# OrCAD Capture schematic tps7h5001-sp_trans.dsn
size Custom; title: TPS7H5001-SP Radiation-Hardness-Assured Si and GaN; rev: B; note: Datasheet: SLVSF07    EVM User Guide: SLVUBZ8; note: Dual Output Controller
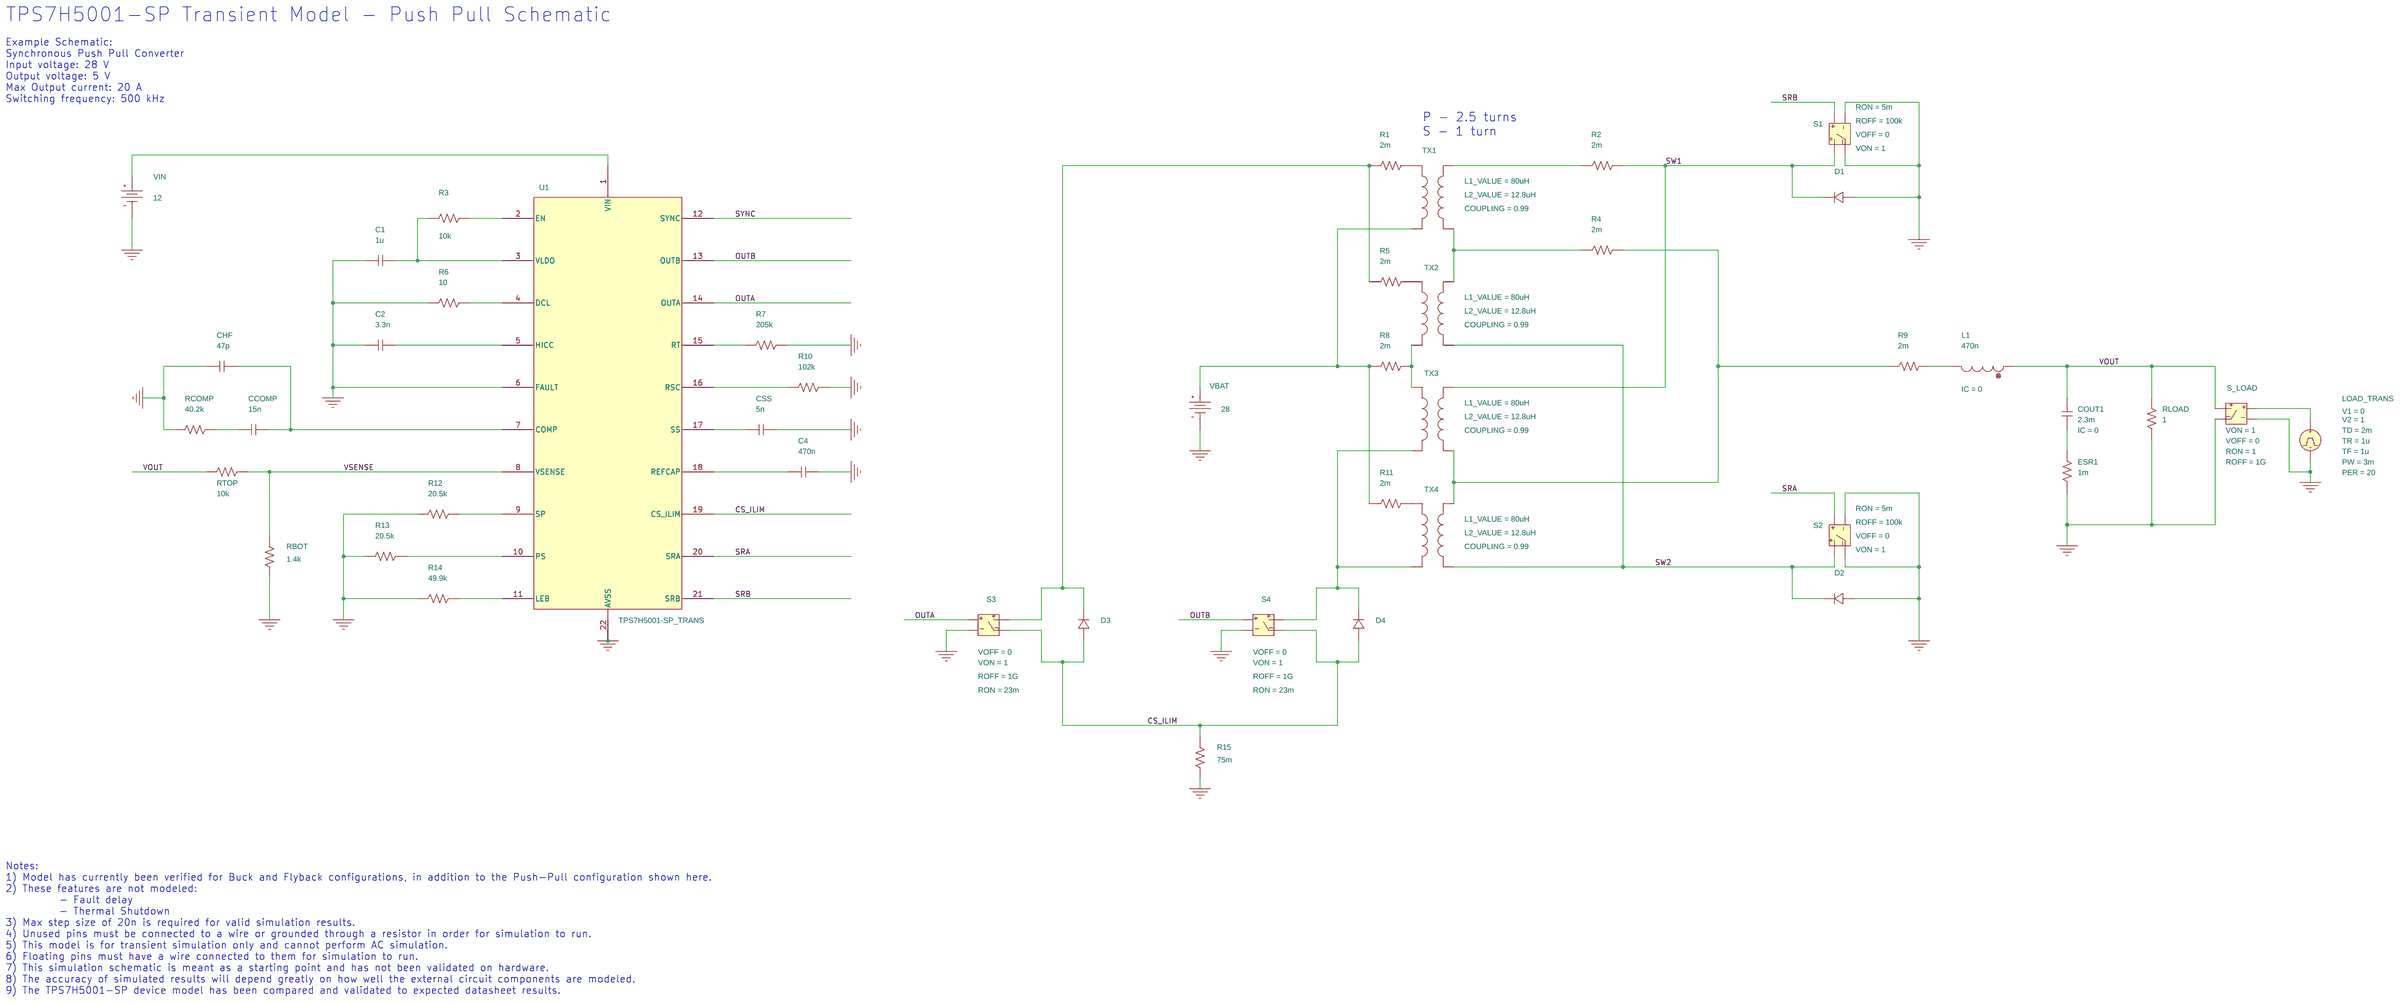
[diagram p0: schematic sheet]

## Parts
C1  1u  [cap196]
C2  3.3n  [cap196]
C4  470n  [cap196]
CCOMP  15n  [cap196]
CHF  47p  [cap196]
COUT1  2.3m  [cap196]
CSS  5n  [cap196]
D1  Dbreak
D2  Dbreak
D3  Dbreak
D4  Dbreak
ESR1  1m  [AXRC05]
L1  470n  [DISC350x175LS200x100034]
LOAD_TRANS  VPULSE
R1  2m  [AXRC05]
R2  2m  [AXRC05]
R3  10k  [AXRC05]
R4  2m  [AXRC05]
R5  2m  [AXRC05]
R6  10  [AXRC05]
R7  205k  [AXRC05]
R8  2m  [AXRC05]
R9  2m  [AXRC05]
R10  102k  [AXRC05]
R11  2m  [AXRC05]
R12  20.5k  [AXRC05]
R13  20.5k  [AXRC05]
R14  49.9k  [AXRC05]
R15  75m  [AXRC05]
RBOT  1.4k  [AXRC05]
RCOMP  40.2k  [AXRC05]
RLOAD  1  [AXRC05]
RTOP  10k  [AXRC05]
S1  S
S2  S
S3  S
S4  S
S_LOAD  S
TX1  XFRM_LINEAR
TX2  XFRM_LINEAR
TX3  XFRM_LINEAR
TX4  XFRM_LINEAR
U1  TPS7H5001-SP_TRANS
VBAT  VDC
VIN  VDC

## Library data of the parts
C1 C2 C4 CCOMP CHF CSS = C
COUT1 = C: IC: 0
D1-D4 = Dbreak
ESR1 R1-R15 RBOT RCOMP RLOAD RTOP = R
L1 = L: IC: 0
LOAD_TRANS = VPULSE: PER: 20; PW: 3m; TD: 2m; TF: 1u; TR: 1u; V1: 0; V2: 1
S1 S2 = S: ROFF: 100k; RON: 5m; VOFF: 0; VON: 1
S3 S4 = S: ROFF: 1G; RON: 23m; VOFF: 0; VON: 1
S_LOAD = S: ROFF: 1G; RON: 1; VOFF: 0; VON: 1
TX1-TX4 = XFRM_LINEAR: COUPLING: 0.99; L1_VALUE: 80uH; L2_VALUE: 12.8uH
U1 = TPS7H5001-SP_TRANS_9
VBAT = VDC: DC: 28
VIN = VDC: DC: 12

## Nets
0: C1.2 C2.2 C4.1 CHF.2 CSS.1 D1.0(1) D2.0(1) ESR1.1 LOAD_TRANS.2(-) R6.2 R7.1 R10.1 R12.2 R13.2 R14.2 R15.2 RBOT.2 RCOMP.2 RLOAD.1 S1.1(2) S1.3(4) S2.1(2) S2.3(4) S3.1(2) S4.1(2) S_LOAD.1(2) S_LOAD.3(4) U1.6(FAULT) U1.22(AVSS) VBAT.1(-) VIN.1(-)
CS_ILIM: D3.0(1) D4.0(1) R15.1 S3.3(4) S4.3(4) U1.19(CS_ILIM)
OUTA: S3.0(1) U1.14(OUTA)
OUTB: S4.0(1) U1.13(OUTB)
SRA: S2.0(1) U1.20(SRA)
SRB: S1.0(1) U1.21(SRB)
SW1: D1.1(2) R2.2 S1.2(3) TX3.3
SW2: D2.1(2) S2.2(3) TX2.4 TX4.4
SYNC: U1.12(SYNC)
VOUT: COUT1.2 L1.1 RLOAD.2 RTOP.2 S_LOAD.2(3)
VSENSE: RBOT.1 RTOP.1 U1.8(VSENSE)
N74628: U1.1(VIN) VIN.0(+)
N74694: D3.1(2) R1.1 R5.1 S3.2(3)
N74740: R2.1 TX1.3
N74872: C1.1 R3.2 U1.3(VLDO)
N74880: R3.1 U1.2(EN)
N74898: R8.1 R11.1 TX1.2 VBAT.0(+)
N74908: R4.1 TX1.4 TX2.3
N74980: R4.2 R9.1 TX3.4 TX4.3
N75098: R6.1 U1.4(DCL)
N75166: C2.1 U1.5(HICC)
N75172: R7.2 U1.15(RT)
N75184: R8.2 TX2.2 TX3.1
N75272: CCOMP.1 CHF.1 U1.7(COMP)
N75314: L1.2 R9.2
N75410: R10.2 U1.16(RSC)
N75596: CCOMP.2 RCOMP.1
N75612: CSS.2 U1.17(SS)
N75704: D4.1(2) S4.2(3) TX3.2 TX4.2
N75720: LOAD_TRANS.1(+) S_LOAD.0(1)
N75812: C4.2 U1.18(REFCAP)
N76020: R12.1 U1.9(SP)
N76162: R13.1 U1.10(PS)
N76312: R14.1 U1.11(LEB)
N16777332: COUT1.1 ESR1.2
N16780805: R11.2 TX4.1
N16780806: R5.2 TX2.1
N16780807: R1.2 TX1.1

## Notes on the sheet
- TPS7H5001-SP Transient Model - Push Pull Schematic
- Example Schematic:
  Synchronous Push Pull Converter
  Input voltage: 28 V
  Output voltage: 5 V
  Max Output current: 20 A
  Switching frequency: 500 kHz
- P - 2.5 turns
  S - 1 turn
- Notes:
  1) Model has currently been verified for Buck and Flyback configurations, in addition to the Push-Pull configuration shown here.
  2) These features are not modeled:
            - Fault delay
            - Thermal Shutdown
  3) Max step size of 20n is required for valid simulation results.
  4) Unused pins must be connected to a wire or grounded through a resistor in order for simulation to run.
  5) This model is for transient simulation only and cannot perform AC simulation.
  6) Floating pins must have a wire connected to them for simulation to run.
  7) This simulation schematic is meant as a starting point and has not been validated on hardware.
  8) The accuracy of simulated results will depend greatly on how well the external circuit components are modeled.
  9) The TPS7H5001-SP device model has been compared and validated to expected datasheet results.
